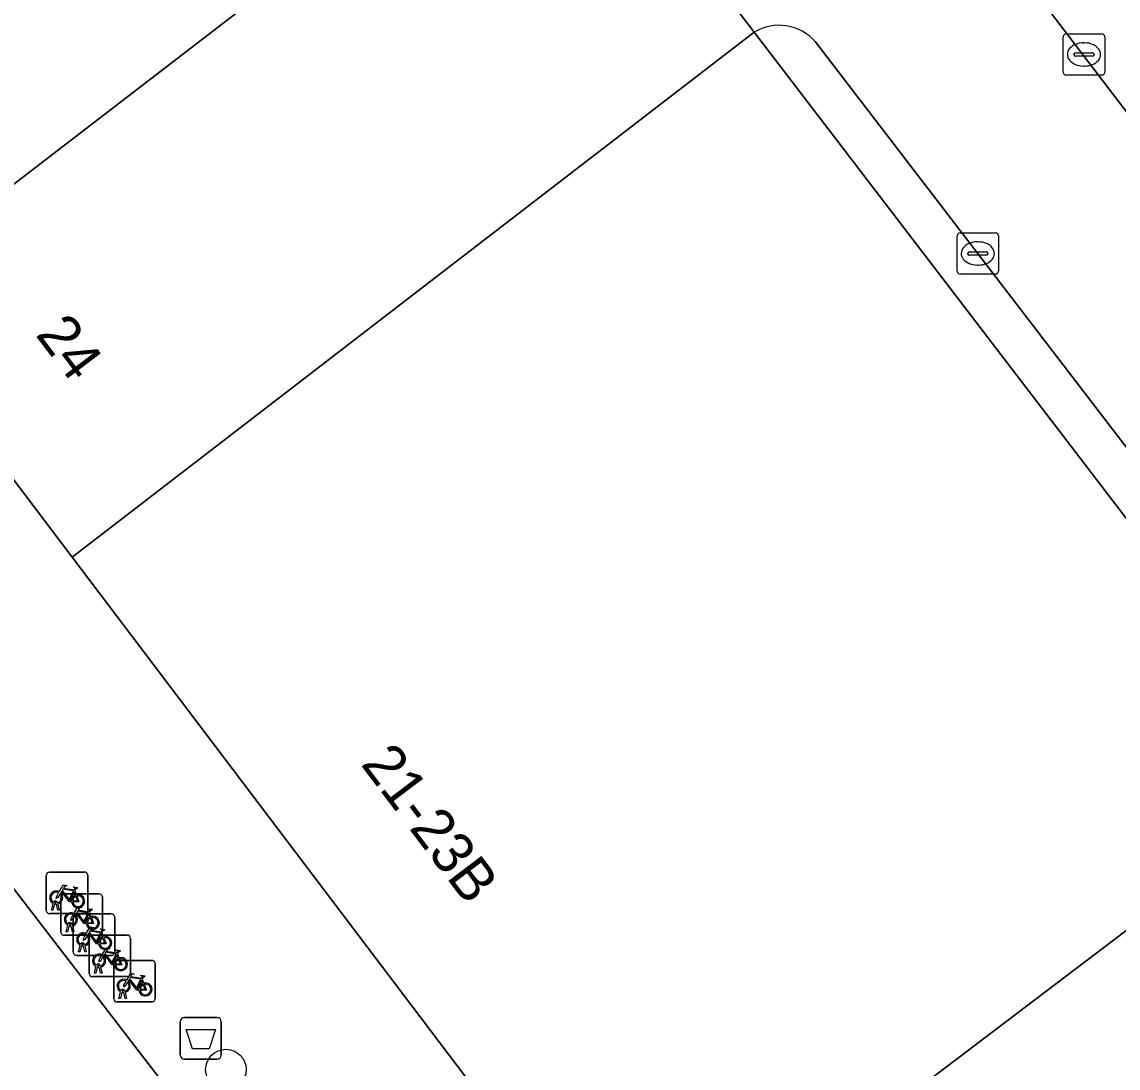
# Model space of a CAD drawing. Extents: x 160157 to 160921, y 381516 to 382045.
# Drawn here: x 160211.35 to 160237.81, y 381618.82 to 381644.06 of the extents above; entities that cross this region are included whole.
import ezdxf

# ---------------------------------------------------------------- set-up
doc = ezdxf.new("R2010")
doc.units = 0
for name, color, linetype in [('IMGEO_Afvalbak', 7, 'Continuous'), ('IMGEO_Boom', 7, 'Continuous'), ('IMGEO_Erf', 7, 'Continuous'), ('IMGEO_Fietsenrek', 7, 'Continuous'), ('IMGEO_Kolk', 7, 'Continuous'), ('IMGEO_Pand', 7, 'Continuous'), ('IMGEO_Pand_nummerreeks', 7, 'Continuous'), ('IMGEO_Parkeervlak_open', 7, 'Continuous'), ('IMGEO_Rijbaan_lokaal_open', 7, 'Continuous'), ('IMGEO_Voetpad_open', 7, 'Continuous')]:
    doc.layers.add(name, color=color, linetype=linetype)

msp = doc.modelspace()

# ---------------------------------------------------------------- linework, layer by layer
at = {"layer": 'IMGEO_Afvalbak'}
for p, q in [((160215.274, 381620.041), (160216.064, 381620.041)), ((160216.064, 381620.041), (160215.274, 381620.041)), ((160215.174, 381619.141), (160215.174, 381619.941)), ((160215.174, 381619.941), (160215.174, 381619.141)), ((160216.164, 381619.941), (160216.164, 381619.141)), ((160216.164, 381619.141), (160216.164, 381619.941)), ((160216.064, 381619.041), (160215.274, 381619.041)), ((160215.274, 381619.041), (160216.064, 381619.041))]:
    msp.add_line(p, q, dxfattribs=at)
msp.add_lwpolyline([(160215.317, 381619.755), (160216.021, 381619.755), (160215.872, 381619.285), (160215.466, 381619.285), (160215.317, 381619.755)], dxfattribs=at)
for centre, start, end in [((160215.274, 381619.941), 90, 180), ((160215.274, 381619.941), 90, 180), ((160216.064, 381619.941), 0, 90), ((160216.064, 381619.941), 360, 90), ((160215.274, 381619.141), 180, 270), ((160215.274, 381619.141), 180, 270), ((160216.064, 381619.141), 270, 0), ((160216.064, 381619.141), 270, 0)]:
    msp.add_arc(centre, 0.1, start, end, dxfattribs=at)
at = {"layer": 'IMGEO_Boom'}
msp.add_circle((160216.276, 381618.786), 0.489, dxfattribs=at)
at = {"layer": 'IMGEO_Erf'}
msp.add_lwpolyline([(160229.719, 381652.76), (160246.171, 381631.2)], dxfattribs=at)
at = {"layer": 'IMGEO_Fietsenrek'}
for p, q in [((160211.941, 381622.625), (160211.941, 381623.466)), ((160211.941, 381623.466), (160211.941, 381622.625)), ((160212.016, 381623.55), (160212.857, 381623.55)), ((160212.857, 381623.55), (160212.016, 381623.55)), ((160212.941, 381623.475), (160212.941, 381622.634)), ((160212.941, 381622.634), (160212.941, 381623.475)), ((160212.295, 381622.1), (160212.295, 381622.941)), ((160212.295, 381622.941), (160212.295, 381622.1)), ((160212.37, 381623.025), (160213.211, 381623.025)), ((160213.211, 381623.025), (160212.37, 381623.025)), ((160212.628, 381623.099), (160212.664, 381623.004)), ((160213.295, 381622.95), (160213.295, 381622.109)), ((160213.295, 381622.109), (160213.295, 381622.95)), ((160212.068, 381622.634), (160212.107, 381622.794)), ((160212.102, 381622.634), (160212.068, 381622.634)), ((160212.137, 381622.782), (160212.102, 381622.634)), ((160212.179, 381622.806), (160212.178, 381622.81)), ((160212.22, 381622.634), (160212.186, 381622.776)), ((160212.21, 381622.817), (160212.211, 381622.81)), ((160212.218, 381622.78), (160212.253, 381622.634)), ((160212.253, 381622.634), (160212.22, 381622.634)), ((160212.866, 381622.55), (160212.025, 381622.55)), ((160212.025, 381622.55), (160212.866, 381622.55)), ((160212.593, 381621.616), (160212.593, 381622.457)), ((160212.593, 381622.457), (160212.593, 381621.616)), ((160212.668, 381622.541), (160213.509, 381622.541)), ((160213.509, 381622.541), (160212.668, 381622.541)), ((160212.982, 381622.574), (160213.018, 381622.479)), ((160213.593, 381622.466), (160213.593, 381621.625)), ((160213.593, 381621.625), (160213.593, 381622.466)), ((160212.422, 381622.109), (160212.461, 381622.269)), ((160212.456, 381622.109), (160212.422, 381622.109)), ((160212.491, 381622.257), (160212.456, 381622.109)), ((160212.533, 381622.281), (160212.532, 381622.285)), ((160212.574, 381622.109), (160212.54, 381622.251)), ((160212.564, 381622.292), (160212.565, 381622.285)), ((160212.572, 381622.255), (160212.607, 381622.109)), ((160212.607, 381622.109), (160212.574, 381622.109)), ((160213.28, 381622.09), (160213.316, 381621.995)), ((160213.22, 381622.025), (160212.379, 381622.025)), ((160212.379, 381622.025), (160213.22, 381622.025)), ((160212.862, 381621.808), (160212.863, 381621.801)), ((160212.974, 381621.104), (160212.974, 381621.945)), ((160212.974, 381621.945), (160212.974, 381621.104)), ((160213.049, 381622.029), (160213.89, 381622.029)), ((160213.89, 381622.029), (160213.049, 381622.029)), ((160213.974, 381621.954), (160213.974, 381621.113)), ((160213.974, 381621.113), (160213.974, 381621.954)), ((160213.518, 381621.541), (160212.677, 381621.541)), ((160212.677, 381621.541), (160213.518, 381621.541)), ((160212.72, 381621.625), (160212.759, 381621.785)), ((160212.754, 381621.625), (160212.72, 381621.625)), ((160212.789, 381621.773), (160212.754, 381621.625)), ((160212.831, 381621.797), (160212.83, 381621.801)), ((160212.872, 381621.625), (160212.838, 381621.767)), ((160212.87, 381621.771), (160212.905, 381621.625)), ((160212.905, 381621.625), (160212.872, 381621.625)), ((160213.661, 381621.578), (160213.697, 381621.483)), ((160213.101, 381621.113), (160213.14, 381621.273)), ((160213.212, 381621.285), (160213.211, 381621.289)), ((160213.243, 381621.296), (160213.244, 381621.289)), ((160213.568, 381620.495), (160213.568, 381621.336)), ((160213.568, 381621.336), (160213.568, 381620.495)), ((160213.643, 381621.42), (160214.484, 381621.42)), ((160214.484, 381621.42), (160213.643, 381621.42)), ((160214.568, 381621.345), (160214.568, 381620.504)), ((160214.568, 381620.504), (160214.568, 381621.345)), ((160213.899, 381621.029), (160213.058, 381621.029)), ((160213.058, 381621.029), (160213.899, 381621.029)), ((160213.135, 381621.113), (160213.101, 381621.113)), ((160213.17, 381621.261), (160213.135, 381621.113)), ((160213.253, 381621.113), (160213.219, 381621.255)), ((160213.251, 381621.259), (160213.286, 381621.113)), ((160213.286, 381621.113), (160213.253, 381621.113)), ((160214.255, 381620.969), (160214.291, 381620.874)), ((160213.695, 381620.504), (160213.734, 381620.664)), ((160213.729, 381620.504), (160213.695, 381620.504)), ((160213.764, 381620.652), (160213.729, 381620.504)), ((160213.806, 381620.676), (160213.805, 381620.68)), ((160213.847, 381620.504), (160213.813, 381620.646)), ((160213.837, 381620.687), (160213.838, 381620.68)), ((160213.845, 381620.65), (160213.88, 381620.504)), ((160213.88, 381620.504), (160213.847, 381620.504)), ((160214.493, 381620.42), (160213.652, 381620.42)), ((160213.652, 381620.42), (160214.493, 381620.42))]:
    msp.add_line(p, q, dxfattribs=at)
for points in [[(160212.254, 381623.076), (160212.349, 381623.24), (160212.435, 381623.226), (160212.437, 381623.217), (160212.381, 381623.206), (160212.354, 381623.161), (160212.61, 381623.12)], [(160212.597, 381623.095), (160212.34, 381623.136), (160212.323, 381623.107), (160212.49, 381622.887), (160212.597, 381623.095)], [(160212.61, 381623.12), (160212.635, 381623.169), (160212.629, 381623.173), (160212.606, 381623.177), (160212.594, 381623.184), (160212.593, 381623.187), (160212.595, 381623.192), (160212.69, 381623.177), (160212.692, 381623.167), (160212.682, 381623.154), (160212.67, 381623.148), (160212.656, 381623.154), (160212.628, 381623.099)], [(160212.275, 381623.024), (160212.223, 381622.934), (160212.183, 381622.909), (160212.184, 381622.956), (160212.239, 381623.05)], [(160212.55, 381622.832), (160212.5, 381622.832), (160212.309, 381623.083), (160212.29, 381623.051)], [(160212.645, 381622.997), (160212.615, 381623.074), (160212.506, 381622.856), (160212.549, 381622.856)], [(160212.579, 381622.856), (160212.699, 381622.855), (160212.655, 381622.969)], [(160212.675, 381622.976), (160212.73, 381622.831), (160212.58, 381622.831)], [(160212.608, 381622.551), (160212.703, 381622.715), (160212.789, 381622.701), (160212.791, 381622.692), (160212.735, 381622.681), (160212.708, 381622.636), (160212.964, 381622.595)], [(160212.951, 381622.57), (160212.694, 381622.611), (160212.677, 381622.582), (160212.844, 381622.362), (160212.951, 381622.57)], [(160212.964, 381622.595), (160212.989, 381622.644), (160212.983, 381622.648), (160212.96, 381622.652), (160212.948, 381622.659), (160212.947, 381622.662), (160212.949, 381622.667), (160213.044, 381622.652), (160213.046, 381622.642), (160213.036, 381622.629), (160213.024, 381622.623), (160213.01, 381622.629), (160212.982, 381622.574)], [(160212.629, 381622.499), (160212.577, 381622.409), (160212.537, 381622.384), (160212.538, 381622.431), (160212.593, 381622.525)], [(160212.904, 381622.307), (160212.854, 381622.307), (160212.663, 381622.558), (160212.644, 381622.526)], [(160212.999, 381622.472), (160212.969, 381622.549), (160212.86, 381622.331), (160212.903, 381622.331)], [(160212.933, 381622.331), (160213.053, 381622.33), (160213.009, 381622.444)], [(160213.029, 381622.451), (160213.084, 381622.306), (160212.934, 381622.306)], [(160212.906, 381622.067), (160213.001, 381622.231), (160213.087, 381622.217), (160213.089, 381622.208), (160213.033, 381622.197), (160213.006, 381622.152), (160213.262, 381622.111)], [(160213.202, 381621.823), (160213.152, 381621.823), (160212.961, 381622.074), (160212.942, 381622.042)], [(160213.249, 381622.086), (160212.992, 381622.127), (160212.975, 381622.098), (160213.142, 381621.878), (160213.249, 381622.086)], [(160213.262, 381622.111), (160213.287, 381622.16), (160213.281, 381622.164), (160213.258, 381622.168), (160213.246, 381622.175), (160213.245, 381622.178), (160213.247, 381622.183), (160213.342, 381622.168), (160213.344, 381622.158), (160213.334, 381622.145), (160213.322, 381622.139), (160213.308, 381622.145), (160213.28, 381622.09)], [(160212.927, 381622.015), (160212.875, 381621.925), (160212.835, 381621.9), (160212.836, 381621.947), (160212.891, 381622.041)], [(160213.297, 381621.988), (160213.267, 381622.065), (160213.158, 381621.847), (160213.201, 381621.847)], [(160213.231, 381621.847), (160213.351, 381621.846), (160213.307, 381621.96)], [(160213.327, 381621.967), (160213.382, 381621.822), (160213.232, 381621.822)], [(160213.287, 381621.555), (160213.382, 381621.719), (160213.468, 381621.705), (160213.47, 381621.696), (160213.414, 381621.685), (160213.387, 381621.64), (160213.643, 381621.599)], [(160213.583, 381621.311), (160213.533, 381621.311), (160213.342, 381621.562), (160213.323, 381621.53)], [(160213.63, 381621.574), (160213.373, 381621.615), (160213.356, 381621.586), (160213.523, 381621.366), (160213.63, 381621.574)], [(160213.678, 381621.476), (160213.648, 381621.553), (160213.539, 381621.335), (160213.582, 381621.335)], [(160213.643, 381621.599), (160213.668, 381621.648), (160213.662, 381621.652), (160213.639, 381621.656), (160213.627, 381621.663), (160213.626, 381621.666), (160213.628, 381621.671), (160213.723, 381621.656), (160213.725, 381621.646), (160213.715, 381621.633), (160213.703, 381621.627), (160213.689, 381621.633), (160213.661, 381621.578)], [(160213.308, 381621.503), (160213.256, 381621.413), (160213.216, 381621.388), (160213.217, 381621.435), (160213.272, 381621.529)], [(160213.612, 381621.335), (160213.732, 381621.334), (160213.688, 381621.448)], [(160213.708, 381621.455), (160213.763, 381621.31), (160213.613, 381621.31)], [(160213.881, 381620.946), (160213.976, 381621.11), (160214.062, 381621.096), (160214.064, 381621.087), (160214.008, 381621.076), (160213.981, 381621.031), (160214.237, 381620.99)], [(160214.237, 381620.99), (160214.262, 381621.039), (160214.256, 381621.043), (160214.233, 381621.047), (160214.221, 381621.054), (160214.22, 381621.057), (160214.222, 381621.062), (160214.317, 381621.047), (160214.319, 381621.037), (160214.309, 381621.024), (160214.297, 381621.018), (160214.283, 381621.024), (160214.255, 381620.969)], [(160213.902, 381620.894), (160213.85, 381620.804), (160213.81, 381620.779), (160213.811, 381620.826), (160213.866, 381620.92)], [(160214.177, 381620.702), (160214.127, 381620.702), (160213.936, 381620.953), (160213.917, 381620.921)], [(160214.224, 381620.965), (160213.967, 381621.006), (160213.95, 381620.977), (160214.117, 381620.757), (160214.224, 381620.965)], [(160214.272, 381620.867), (160214.242, 381620.944), (160214.133, 381620.726), (160214.176, 381620.726)], [(160214.206, 381620.726), (160214.326, 381620.725), (160214.282, 381620.839)], [(160214.302, 381620.846), (160214.357, 381620.701), (160214.207, 381620.701)]]:
    msp.add_lwpolyline(points, dxfattribs=at)
for centre, radius, start, end in [((160212.019, 381623.472), 0.0779, 92.4484, 184.2845), ((160212.019, 381623.472), 0.0779, 92.4484, 184.2845), ((160212.863, 381623.472), 0.0779, 2.4484, 94.2845), ((160212.863, 381623.472), 0.0779, 2.4484, 94.2845), ((160212.181, 381622.935), 0.159, 62.6766, 242.1369), ((160212.181, 381622.935), 0.129, 63.3192, 238.903), ((160212.181, 381622.935), 0.129, 283.6043, 43.4302), ((160212.181, 381622.935), 0.159, 283.5766, 46.6042), ((160212.373, 381622.947), 0.0779, 92.4484, 184.2845), ((160212.373, 381622.947), 0.0779, 92.4484, 184.2845), ((160212.708, 381622.851), 0.159, 113.3408, 178.3217), ((160212.708, 381622.851), 0.159, 187.0065, 105.7708), ((160212.708, 381622.851), 0.129, 113.923, 177.9556), ((160212.708, 381622.851), 0.129, 188.6715, 104.5883), ((160213.217, 381622.947), 0.0779, 2.4484, 94.2845), ((160213.217, 381622.947), 0.0779, 2.4484, 94.2845), ((160212.019, 381622.628), 0.0779, 182.4484, 274.2845), ((160212.019, 381622.628), 0.0779, 182.4484, 274.2845), ((160212.161, 381622.806), 0.0499, 12.8025, 158.6934), ((160212.181, 381622.935), 0.159, 253.9967, 271.7867), ((160212.161, 381622.806), 0.0174, 12.8025, 163.4502), ((160212.181, 381622.935), 0.129, 253.415, 269.0204), ((160212.863, 381622.628), 0.0779, 272.4484, 4.2845), ((160212.863, 381622.628), 0.0779, 272.4484, 4.2845), ((160212.535, 381622.41), 0.159, 62.6766, 242.1369), ((160212.535, 381622.41), 0.129, 63.3192, 238.903), ((160212.515, 381622.281), 0.0499, 12.8025, 158.6934), ((160212.535, 381622.41), 0.129, 283.6043, 43.4302), ((160212.535, 381622.41), 0.159, 283.5766, 46.6042), ((160212.671, 381622.463), 0.0779, 92.4484, 184.2845), ((160212.671, 381622.463), 0.0779, 92.4484, 184.2845), ((160213.062, 381622.326), 0.159, 113.3408, 178.3217), ((160213.062, 381622.326), 0.159, 187.0065, 105.7708), ((160213.062, 381622.326), 0.129, 113.923, 177.9556), ((160213.062, 381622.326), 0.129, 188.6715, 104.5883), ((160213.515, 381622.463), 0.0779, 2.4484, 94.2845), ((160213.515, 381622.463), 0.0779, 2.4484, 94.2845), ((160212.373, 381622.103), 0.0779, 182.4484, 274.2845), ((160212.373, 381622.103), 0.0779, 182.4484, 274.2845), ((160212.535, 381622.41), 0.159, 253.9967, 271.7867), ((160212.515, 381622.281), 0.0174, 12.8025, 163.4502), ((160212.535, 381622.41), 0.129, 253.415, 269.0204), ((160212.833, 381621.926), 0.159, 62.6766, 242.1369), ((160213.217, 381622.103), 0.0779, 272.4484, 4.2845), ((160213.217, 381622.103), 0.0779, 272.4484, 4.2845), ((160212.833, 381621.926), 0.129, 63.3192, 238.903), ((160212.813, 381621.797), 0.0499, 12.8025, 158.6934), ((160212.813, 381621.797), 0.0174, 12.8025, 163.4502), ((160212.833, 381621.926), 0.129, 253.415, 269.0204), ((160212.833, 381621.926), 0.129, 283.6043, 43.4302), ((160212.833, 381621.926), 0.159, 283.5766, 46.6042), ((160213.052, 381621.951), 0.0779, 92.4484, 184.2845), ((160213.052, 381621.951), 0.0779, 92.4484, 184.2845), ((160213.36, 381621.842), 0.159, 113.3408, 178.3217), ((160213.36, 381621.842), 0.159, 187.0065, 105.7708), ((160213.36, 381621.842), 0.129, 113.923, 177.9556), ((160213.36, 381621.842), 0.129, 188.6715, 104.5883), ((160213.896, 381621.951), 0.0779, 2.4484, 94.2845), ((160213.896, 381621.951), 0.0779, 2.4484, 94.2845), ((160212.671, 381621.619), 0.0779, 182.4484, 274.2845), ((160212.671, 381621.619), 0.0779, 182.4484, 274.2845), ((160212.833, 381621.926), 0.159, 253.9967, 271.7867), ((160213.214, 381621.414), 0.159, 62.6766, 242.1369), ((160213.214, 381621.414), 0.129, 63.3192, 238.903), ((160213.515, 381621.619), 0.0779, 272.4484, 4.2845), ((160213.515, 381621.619), 0.0779, 272.4484, 4.2845), ((160213.194, 381621.285), 0.0499, 12.8025, 158.6934), ((160213.194, 381621.285), 0.0174, 12.8025, 163.4502), ((160213.214, 381621.414), 0.129, 253.415, 269.0204), ((160213.214, 381621.414), 0.129, 283.6043, 43.4302), ((160213.214, 381621.414), 0.159, 283.5766, 46.6042), ((160213.646, 381621.342), 0.0779, 92.4484, 184.2845), ((160213.646, 381621.342), 0.0779, 92.4484, 184.2845), ((160213.741, 381621.33), 0.159, 113.3408, 178.3217), ((160213.741, 381621.33), 0.159, 187.0065, 105.7708), ((160213.741, 381621.33), 0.129, 113.923, 177.9556), ((160213.741, 381621.33), 0.129, 188.6715, 104.5883), ((160214.49, 381621.342), 0.0779, 2.4484, 94.2845), ((160214.49, 381621.342), 0.0779, 2.4484, 94.2845), ((160213.052, 381621.107), 0.0779, 182.4484, 274.2845), ((160213.052, 381621.107), 0.0779, 182.4484, 274.2845), ((160213.214, 381621.414), 0.159, 253.9967, 271.7867), ((160213.896, 381621.107), 0.0779, 272.4484, 4.2845), ((160213.896, 381621.107), 0.0779, 272.4484, 4.2845), ((160213.808, 381620.805), 0.159, 62.6766, 242.1369), ((160213.808, 381620.805), 0.129, 63.3192, 238.903), ((160213.808, 381620.805), 0.129, 283.6043, 43.4302), ((160213.808, 381620.805), 0.159, 283.5766, 46.6042), ((160214.335, 381620.721), 0.159, 113.3408, 178.3217), ((160214.335, 381620.721), 0.159, 187.0065, 105.7708), ((160214.335, 381620.721), 0.129, 113.923, 177.9556), ((160214.335, 381620.721), 0.129, 188.6715, 104.5883), ((160213.646, 381620.498), 0.0779, 182.4484, 274.2845), ((160213.646, 381620.498), 0.0779, 182.4484, 274.2845), ((160213.788, 381620.676), 0.0499, 12.8025, 158.6934), ((160213.808, 381620.805), 0.159, 253.9967, 271.7867), ((160213.788, 381620.676), 0.0174, 12.8025, 163.4502), ((160213.808, 381620.805), 0.129, 253.415, 269.0204), ((160214.49, 381620.498), 0.0779, 272.4484, 4.2845), ((160214.49, 381620.498), 0.0779, 272.4484, 4.2845)]:
    msp.add_arc(centre, radius, start, end, dxfattribs=at)
at = {"layer": 'IMGEO_Kolk'}
for p, q in [((160236.559, 381643.771), (160237.411, 381643.771)), ((160236.484, 381642.845), (160236.484, 381643.697)), ((160236.972, 381643.551), (160236.997, 381643.551)), ((160237.485, 381643.697), (160237.485, 381642.845)), ((160236.743, 381643.265), (160236.743, 381643.277)), ((160236.786, 381643.314), (160237.184, 381643.314)), ((160237.227, 381643.277), (160237.227, 381643.265)), ((160237.181, 381643.228), (160236.783, 381643.228)), ((160236.995, 381642.991), (160236.97, 381642.991)), ((160237.411, 381642.771), (160236.559, 381642.771)), ((160233.921, 381638.045), (160233.921, 381638.897)), ((160233.996, 381638.971), (160234.848, 381638.971)), ((160234.409, 381638.751), (160234.434, 381638.751)), ((160234.922, 381638.897), (160234.922, 381638.045)), ((160234.18, 381638.465), (160234.18, 381638.477)), ((160234.223, 381638.514), (160234.621, 381638.514)), ((160234.664, 381638.477), (160234.664, 381638.465)), ((160234.618, 381638.428), (160234.22, 381638.428)), ((160234.848, 381637.971), (160233.996, 381637.971)), ((160234.432, 381638.191), (160234.407, 381638.191))]:
    msp.add_line(p, q, dxfattribs=at)
for points in [[(160236.559, 381643.771), (160237.411, 381643.771)], [(160236.484, 381642.845), (160236.484, 381643.697)], [(160237.485, 381643.697), (160237.485, 381642.845)], [(160237.411, 381642.771), (160236.559, 381642.771)], [(160233.921, 381638.045), (160233.921, 381638.897)], [(160233.996, 381638.971), (160234.848, 381638.971)], [(160234.922, 381638.897), (160234.922, 381638.045)], [(160234.848, 381637.971), (160233.996, 381637.971)]]:
    msp.add_lwpolyline(points, dxfattribs=at)
for centre, radius, start, end in [((160236.561, 381643.695), 0.0765, 91.552, 178.448), ((160236.561, 381643.695), 0.0765, 91.552, 178.448), ((160237.409, 381643.695), 0.0765, 1.552, 88.448), ((160237.409, 381643.695), 0.0765, 1.552, 88.448), ((160236.783, 381643.274), 0.0403, 85.8775, 175.7526), ((160236.78, 381643.264), 0.0366, 178.938, 274.7102), ((160237.184, 381643.271), 0.043, 264.8664, 352.4533), ((160237.188, 381643.276), 0.0386, 1.7309, 96.639), ((160236.561, 381642.847), 0.0765, 181.552, 268.448), ((160236.561, 381642.847), 0.0765, 181.552, 268.448), ((160237.409, 381642.847), 0.0765, 271.552, 358.448), ((160237.409, 381642.847), 0.0765, 271.552, 358.448), ((160233.998, 381638.895), 0.0765, 91.552, 178.448), ((160233.998, 381638.895), 0.0765, 91.552, 178.448), ((160234.846, 381638.895), 0.0765, 1.552, 88.448), ((160234.846, 381638.895), 0.0765, 1.552, 88.448), ((160234.22, 381638.474), 0.0403, 85.8775, 175.7526), ((160234.625, 381638.476), 0.0386, 1.7309, 96.639), ((160234.217, 381638.464), 0.0366, 178.938, 274.7102), ((160234.621, 381638.471), 0.043, 264.8664, 352.4533), ((160233.998, 381638.047), 0.0765, 181.552, 268.448), ((160233.998, 381638.047), 0.0765, 181.552, 268.448), ((160234.846, 381638.047), 0.0765, 271.552, 358.448), ((160234.846, 381638.047), 0.0765, 271.552, 358.448)]:
    msp.add_arc(centre, radius, start, end, dxfattribs=at)
for centre, major_axis, ratio, start_param, end_param in [((160236.971, 381643.271), (-0.387, 0.002), 0.722429, 4.712389, 7.853982), ((160236.996, 381643.271), (-0.39, 0.002), 0.717154, 1.570796, 4.712389), ((160234.408, 381638.471), (-0.387, 0.002), 0.722429, 4.712389, 7.853982), ((160234.433, 381638.471), (-0.39, 0.002), 0.717154, 1.570796, 4.712389)]:
    msp.add_ellipse(centre, major_axis=major_axis, ratio=ratio, start_param=start_param, end_param=end_param, dxfattribs=at)
at = {"layer": 'IMGEO_Pand'}
msp.add_lwpolyline([(160206.994, 381638.502), (160207.737, 381637.521), (160224.171, 381650.152)], dxfattribs=at)
for points in [[(160207.737, 381637.521), (160212.568, 381631.144), (160229.025, 381643.813), (160224.171, 381650.152)], [(160226.18, 381613.178), (160242.824, 381625.788), (160229.025, 381643.813), (160212.568, 381631.144)], [(160251.229, 381614.81), (160249.159, 381617.513), (160242.824, 381625.788), (160226.18, 381613.178), (160232.975, 381604.21), (160234.601, 381602.064)]]:
    msp.add_lwpolyline(points, close=True, dxfattribs=at)
at = {"layer": 'IMGEO_Parkeervlak_open'}
msp.add_lwpolyline([(160228.264, 381600.92), (160200.851, 381636.528)], dxfattribs=at)
at = {"layer": 'IMGEO_Rijbaan_lokaal_open'}
msp.add_lwpolyline([(160230.499, 381643.584), (160250.004, 381618.161), (160252.688, 381614.66), (160256.595, 381617.668), (160246.171, 381631.2), (160229.719, 381652.76), (160228.618, 381652.681), (160226.57, 381651.942), (160224.171, 381650.152), (160229.025, 381643.813)], dxfattribs=at)
msp.add_arc((160229.622, 381642.795), 1.18, 41.9555, 120.3828, dxfattribs=at)
at = {"layer": 'IMGEO_Voetpad_open'}
for points in [[(160229.025, 381643.813), (160242.824, 381625.788), (160249.159, 381617.513), (160251.229, 381614.81), (160234.601, 381602.064), (160232.975, 381604.21), (160228.264, 381600.92)], [(160247.077, 381600.838), (160248.811, 381602.669), (160249.02, 381602.89), (160250.642, 381604.603), (160250.836, 381604.803), (160255.71, 381609.286), (160256.276, 381609.836), (160252.688, 381614.66), (160250.004, 381618.161), (160230.499, 381643.584)], [(160212.568, 381631.144), (160207.737, 381637.521), (160206.994, 381638.502)], [(160200.851, 381636.528), (160228.264, 381600.92), (160232.975, 381604.21), (160226.18, 381613.178), (160212.568, 381631.144)]]:
    msp.add_lwpolyline(points, dxfattribs=at)
msp.add_arc((160229.622, 381642.795), 1.18, 41.9555, 120.3828, dxfattribs=at)

# ---------------------------------------------------------------- texts
at = {"layer": 'IMGEO_Pand_nummerreeks'}
for s, p in [('24', (160211.664, 381636.511)), ('21-23B', (160219.513, 381626.151))]:
    msp.add_text(s, height=1, rotation=307.1496, dxfattribs=at).set_placement(p)

doc.saveas('drawing.dxf')
